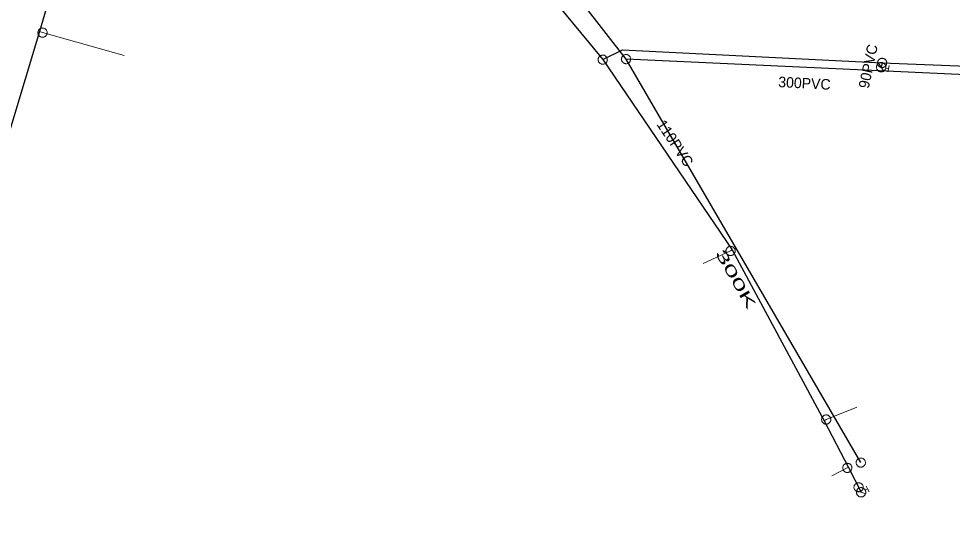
# Model space of a CAD drawing. Extents: x -741806 to -738704, y -1059275 to -1055387.
# Drawn here: x -740471.9 to -740383.1, y -1057505.9 to -1057458.7 of the extents above; entities that cross this region are included whole.
import ezdxf

# ---------------------------------------------------------------- set-up
doc = ezdxf.new("R2010")
doc.units = 0
doc.header["$LTSCALE"] = 0.4
for name, color, linetype, lineweight in [('2', 7, 'Continuous', 25), ('21', 7, 'Continuous', 13), ('3', 7, 'Continuous', 13), ('50', 7, 'Continuous', 13), ('51', 7, 'Continuous', 13), ('52', 7, 'Continuous', 25)]:
    doc.layers.add(name, color=color, linetype=linetype, lineweight=lineweight)
doc.layers.add('5', color=7, linetype='Continuous')
doc.layers.add('53', color=7, linetype='Continuous')

msp = doc.modelspace()

# ---------------------------------------------------------------- linework, layer by layer
at = {"layer": '2'}
for points in [[(-740391.767, -1057500.943), (-740414.1, -1057462.575), (-740436.364, -1057433.99), (-740463.206, -1057418.767)], [(-740262.282, -1057468.655), (-740309.544, -1057466.825), (-740348.973, -1057465.28), (-740379.006, -1057464.2), (-740414.1, -1057462.575)]]:
    msp.add_lwpolyline(points, dxfattribs=at)
at = {"layer": '21'}
for points in [[(-740469.89, -1057459.936), (-740469.611, -1057460.054), (-740461.851, -1057462.24)], [(-740404.013, -1057480.723), (-740404.157, -1057480.815), (-740406.774, -1057482.007)], [(-740395.265, -1057496.955), (-740395.061, -1057496.845), (-740392.149, -1057495.669)], [(-740392.936, -1057501.415), (-740393.052, -1057501.45), (-740394.509, -1057502.191)]]:
    msp.add_lwpolyline(points, dxfattribs=at)
at = {"layer": '3'}
for points in [[(-740414.319, -1057462.196), (-740414.357, -1057462.221), (-740414.392, -1057462.25), (-740414.425, -1057462.283), (-740414.453, -1057462.318), (-740414.478, -1057462.356), (-740414.499, -1057462.398), (-740414.515, -1057462.44), (-740414.527, -1057462.485), (-740414.533, -1057462.53), (-740414.536, -1057462.575), (-740414.533, -1057462.621), (-740414.527, -1057462.667), (-740414.514, -1057462.71), (-740414.498, -1057462.753), (-740414.477, -1057462.794), (-740414.452, -1057462.833), (-740414.422, -1057462.868), (-740414.391, -1057462.9), (-740414.354, -1057462.929), (-740414.316, -1057462.954), (-740414.275, -1057462.974), (-740414.233, -1057462.99), (-740414.188, -1057463.002), (-740414.143, -1057463.009), (-740414.097, -1057463.011), (-740414.051, -1057463.008), (-740414.006, -1057463.002), (-740413.962, -1057462.989), (-740413.919, -1057462.973), (-740413.878, -1057462.951), (-740413.84, -1057462.927), (-740413.805, -1057462.898), (-740413.772, -1057462.865), (-740413.744, -1057462.829), (-740413.719, -1057462.792), (-740413.698, -1057462.75), (-740413.682, -1057462.708), (-740413.67, -1057462.663), (-740413.664, -1057462.618), (-740413.661, -1057462.573), (-740413.664, -1057462.527), (-740413.671, -1057462.481), (-740413.683, -1057462.437), (-740413.699, -1057462.395), (-740413.721, -1057462.354), (-740413.745, -1057462.315), (-740413.774, -1057462.28), (-740413.807, -1057462.248), (-740413.843, -1057462.219), (-740413.882, -1057462.194), (-740413.922, -1057462.174), (-740413.965, -1057462.157), (-740414.009, -1057462.146), (-740414.054, -1057462.139), (-740414.1, -1057462.137), (-740414.146, -1057462.139), (-740414.191, -1057462.146), (-740414.236, -1057462.159), (-740414.278, -1057462.175), (-740414.319, -1057462.195)], [(-740391.986, -1057500.564), (-740392.024, -1057500.589), (-740392.059, -1057500.618), (-740392.092, -1057500.651), (-740392.12, -1057500.686), (-740392.145, -1057500.724), (-740392.166, -1057500.766), (-740392.182, -1057500.808), (-740392.194, -1057500.853), (-740392.2, -1057500.898), (-740392.203, -1057500.943), (-740392.2, -1057500.989), (-740392.194, -1057501.035), (-740392.181, -1057501.078), (-740392.165, -1057501.121), (-740392.144, -1057501.162), (-740392.119, -1057501.201), (-740392.089, -1057501.236), (-740392.058, -1057501.268), (-740392.021, -1057501.297), (-740391.983, -1057501.322), (-740391.942, -1057501.342), (-740391.9, -1057501.358), (-740391.855, -1057501.37), (-740391.81, -1057501.377), (-740391.764, -1057501.379), (-740391.718, -1057501.376), (-740391.673, -1057501.37), (-740391.629, -1057501.357), (-740391.586, -1057501.341), (-740391.545, -1057501.319), (-740391.507, -1057501.295), (-740391.472, -1057501.266), (-740391.439, -1057501.233), (-740391.411, -1057501.197), (-740391.386, -1057501.16), (-740391.365, -1057501.118), (-740391.349, -1057501.076), (-740391.337, -1057501.031), (-740391.331, -1057500.986), (-740391.328, -1057500.941), (-740391.331, -1057500.895), (-740391.338, -1057500.849), (-740391.35, -1057500.805), (-740391.366, -1057500.763), (-740391.388, -1057500.722), (-740391.412, -1057500.683), (-740391.441, -1057500.648), (-740391.474, -1057500.616), (-740391.51, -1057500.587), (-740391.549, -1057500.562), (-740391.589, -1057500.542), (-740391.632, -1057500.525), (-740391.676, -1057500.514), (-740391.721, -1057500.507), (-740391.767, -1057500.505), (-740391.813, -1057500.507), (-740391.858, -1057500.514), (-740391.903, -1057500.527), (-740391.945, -1057500.543), (-740391.986, -1057500.563)]]:
    msp.add_lwpolyline(points, dxfattribs=at)
at = {"layer": '50'}
for p, q in [((-740389.831, -1057463.35), (-740390.075, -1057462.973)), ((-740389.831, -1057463.35), (-740389.591, -1057463.723)), ((-740389.393, -1057463.442), (-740389.148, -1057463.494)), ((-740389.212, -1057463.794), (-740389.148, -1057463.494)), ((-740389.084, -1057463.193), (-740389.148, -1057463.494)), ((-740391.345, -1057503.564), (-740391.121, -1057503.45)), ((-740391.261, -1057503.175), (-740391.121, -1057503.45)), ((-740390.982, -1057503.723), (-740391.121, -1057503.45)), ((-740391.743, -1057503.768), (-740392.169, -1057503.629)), ((-740391.743, -1057503.768), (-740391.322, -1057503.907))]:
    msp.add_line(p, q, dxfattribs=at)
for points in [[(-740389.927, -1057463.783), (-740389.879, -1057463.79), (-740389.833, -1057463.795), (-740389.785, -1057463.792), (-740389.739, -1057463.784), (-740389.696, -1057463.774), (-740389.651, -1057463.756), (-740389.61, -1057463.735), (-740389.569, -1057463.71), (-740389.533, -1057463.682), (-740389.501, -1057463.648), (-740389.471, -1057463.612), (-740389.443, -1057463.574), (-740389.424, -1057463.531), (-740389.406, -1057463.488), (-740389.394, -1057463.444), (-740389.387, -1057463.398), (-740389.383, -1057463.353), (-740389.386, -1057463.305), (-740389.393, -1057463.259), (-740389.405, -1057463.212), (-740389.422, -1057463.17), (-740389.442, -1057463.128), (-740389.468, -1057463.089), (-740389.496, -1057463.053), (-740389.529, -1057463.018), (-740389.565, -1057462.988), (-740389.604, -1057462.963), (-740389.646, -1057462.94), (-740389.69, -1057462.926), (-740389.733, -1057462.91), (-740389.781, -1057462.903), (-740389.828, -1057462.901), (-740389.872, -1057462.903), (-740389.92, -1057462.909), (-740389.965, -1057462.922), (-740390.009, -1057462.937), (-740390.049, -1057462.959), (-740390.09, -1057462.984), (-740390.128, -1057463.014), (-740390.159, -1057463.047), (-740390.189, -1057463.084), (-740390.214, -1057463.123), (-740390.237, -1057463.162), (-740390.255, -1057463.208), (-740390.267, -1057463.253), (-740390.274, -1057463.298), (-740390.276, -1057463.345), (-740390.274, -1057463.392), (-740390.268, -1057463.438), (-740390.255, -1057463.484), (-740390.24, -1057463.526), (-740390.218, -1057463.57), (-740390.194, -1057463.608), (-740390.166, -1057463.644), (-740390.131, -1057463.676), (-740390.096, -1057463.708), (-740390.057, -1057463.734), (-740390.015, -1057463.753), (-740389.972, -1057463.77)], [(-740391.544, -1057504.165), (-740391.502, -1057504.14), (-740391.463, -1057504.115), (-740391.428, -1057504.082), (-740391.398, -1057504.048), (-740391.371, -1057504.012), (-740391.347, -1057503.97), (-740391.328, -1057503.928), (-740391.312, -1057503.883), (-740391.301, -1057503.838), (-740391.298, -1057503.791), (-740391.297, -1057503.745), (-740391.3, -1057503.698), (-740391.312, -1057503.652), (-740391.326, -1057503.608), (-740391.344, -1057503.565), (-740391.367, -1057503.526), (-740391.392, -1057503.488), (-740391.425, -1057503.453), (-740391.46, -1057503.421), (-740391.498, -1057503.393), (-740391.538, -1057503.37), (-740391.58, -1057503.35), (-740391.625, -1057503.336), (-740391.669, -1057503.326), (-740391.717, -1057503.32), (-740391.763, -1057503.319), (-740391.809, -1057503.324), (-740391.856, -1057503.333), (-740391.9, -1057503.349), (-740391.943, -1057503.365), (-740391.985, -1057503.389), (-740392.022, -1057503.417), (-740392.055, -1057503.447), (-740392.089, -1057503.482), (-740392.116, -1057503.52), (-740392.14, -1057503.559), (-740392.158, -1057503.602), (-740392.175, -1057503.647), (-740392.184, -1057503.694), (-740392.188, -1057503.739), (-740392.188, -1057503.787), (-740392.183, -1057503.833), (-740392.176, -1057503.877), (-740392.161, -1057503.925), (-740392.143, -1057503.967), (-740392.119, -1057504.007), (-740392.091, -1057504.044), (-740392.06, -1057504.08), (-740392.027, -1057504.111), (-740391.987, -1057504.139), (-740391.949, -1057504.162), (-740391.905, -1057504.182), (-740391.862, -1057504.196), (-740391.817, -1057504.207), (-740391.77, -1057504.21), (-740391.723, -1057504.213), (-740391.676, -1057504.208), (-740391.631, -1057504.197), (-740391.587, -1057504.183)]]:
    msp.add_lwpolyline(points, close=True, dxfattribs=at)
at = {"layer": '51'}
for points in [[(-740469.174, -1057460.054), (-740469.176, -1057460.009), (-740469.183, -1057459.964), (-740469.195, -1057459.919), (-740469.211, -1057459.877), (-740469.232, -1057459.836), (-740469.257, -1057459.797), (-740469.286, -1057459.762), (-740469.318, -1057459.729), (-740469.354, -1057459.701), (-740469.392, -1057459.676), (-740469.433, -1057459.655), (-740469.476, -1057459.638), (-740469.52, -1057459.626), (-740469.565, -1057459.619), (-740469.611, -1057459.617), (-740469.657, -1057459.619), (-740469.702, -1057459.626), (-740469.746, -1057459.638), (-740469.789, -1057459.655), (-740469.83, -1057459.676), (-740469.868, -1057459.701), (-740469.904, -1057459.729), (-740469.936, -1057459.762), (-740469.965, -1057459.797), (-740469.99, -1057459.836), (-740470.011, -1057459.877), (-740470.027, -1057459.919), (-740470.039, -1057459.964), (-740470.046, -1057460.009), (-740470.049, -1057460.055), (-740470.046, -1057460.1), (-740470.039, -1057460.145), (-740470.027, -1057460.19), (-740470.011, -1057460.232), (-740469.99, -1057460.273), (-740469.965, -1057460.312), (-740469.936, -1057460.347), (-740469.904, -1057460.38), (-740469.868, -1057460.408), (-740469.83, -1057460.433), (-740469.789, -1057460.454), (-740469.746, -1057460.471), (-740469.702, -1057460.482), (-740469.657, -1057460.49), (-740469.611, -1057460.492), (-740469.565, -1057460.49), (-740469.52, -1057460.482), (-740469.476, -1057460.471), (-740469.433, -1057460.454), (-740469.392, -1057460.433), (-740469.354, -1057460.408), (-740469.318, -1057460.38), (-740469.286, -1057460.347), (-740469.257, -1057460.312), (-740469.232, -1057460.273), (-740469.211, -1057460.232), (-740469.195, -1057460.19), (-740469.183, -1057460.145), (-740469.176, -1057460.1), (-740469.174, -1057460.055)], [(-740389.301, -1057462.955), (-740389.301, -1057462.91), (-740389.306, -1057462.864), (-740389.315, -1057462.819), (-740389.329, -1057462.776), (-740389.348, -1057462.734), (-740389.371, -1057462.694), (-740389.398, -1057462.658), (-740389.429, -1057462.623), (-740389.463, -1057462.593), (-740389.5, -1057462.566), (-740389.54, -1057462.543), (-740389.582, -1057462.524), (-740389.625, -1057462.51), (-740389.67, -1057462.501), (-740389.716, -1057462.497), (-740389.762, -1057462.496), (-740389.807, -1057462.501), (-740389.852, -1057462.511), (-740389.895, -1057462.526), (-740389.937, -1057462.545), (-740389.977, -1057462.568), (-740390.014, -1057462.594), (-740390.048, -1057462.625), (-740390.078, -1057462.659), (-740390.105, -1057462.696), (-740390.128, -1057462.736), (-740390.146, -1057462.777), (-740390.161, -1057462.822), (-740390.17, -1057462.866), (-740390.175, -1057462.912), (-740390.174, -1057462.957), (-740390.17, -1057463.003), (-740390.16, -1057463.048), (-740390.146, -1057463.091), (-740390.127, -1057463.133), (-740390.104, -1057463.173), (-740390.077, -1057463.209), (-740390.046, -1057463.244), (-740390.012, -1057463.274), (-740389.975, -1057463.301), (-740389.935, -1057463.324), (-740389.893, -1057463.343), (-740389.85, -1057463.356), (-740389.805, -1057463.366), (-740389.759, -1057463.37), (-740389.713, -1057463.371), (-740389.668, -1057463.365), (-740389.623, -1057463.356), (-740389.58, -1057463.341), (-740389.538, -1057463.322), (-740389.498, -1057463.299), (-740389.461, -1057463.273), (-740389.428, -1057463.242), (-740389.397, -1057463.208), (-740389.37, -1057463.171), (-740389.347, -1057463.131), (-740389.329, -1057463.09), (-740389.315, -1057463.045), (-740389.305, -1057463.001), (-740389.301, -1057462.956)], [(-740404.526, -1057481.048), (-740404.5, -1057481.085), (-740404.47, -1057481.119), (-740404.436, -1057481.15), (-740404.4, -1057481.177), (-740404.361, -1057481.201), (-740404.319, -1057481.22), (-740404.276, -1057481.235), (-740404.231, -1057481.245), (-740404.185, -1057481.25), (-740404.14, -1057481.251), (-740404.094, -1057481.246), (-740404.049, -1057481.238), (-740404.005, -1057481.225), (-740403.963, -1057481.206), (-740403.923, -1057481.183), (-740403.885, -1057481.157), (-740403.851, -1057481.127), (-740403.82, -1057481.094), (-740403.793, -1057481.056), (-740403.77, -1057481.017), (-740403.751, -1057480.975), (-740403.735, -1057480.932), (-740403.726, -1057480.887), (-740403.72, -1057480.842), (-740403.72, -1057480.796), (-740403.724, -1057480.75), (-740403.733, -1057480.706), (-740403.747, -1057480.662), (-740403.765, -1057480.62), (-740403.787, -1057480.579), (-740403.814, -1057480.543), (-740403.844, -1057480.509), (-740403.878, -1057480.477), (-740403.914, -1057480.45), (-740403.953, -1057480.426), (-740403.995, -1057480.407), (-740404.039, -1057480.393), (-740404.083, -1057480.382), (-740404.129, -1057480.378), (-740404.174, -1057480.377), (-740404.22, -1057480.381), (-740404.265, -1057480.389), (-740404.308, -1057480.404), (-740404.351, -1057480.421), (-740404.391, -1057480.444), (-740404.429, -1057480.47), (-740404.462, -1057480.501), (-740404.494, -1057480.534), (-740404.521, -1057480.571), (-740404.544, -1057480.611), (-740404.563, -1057480.652), (-740404.579, -1057480.695), (-740404.588, -1057480.74), (-740404.594, -1057480.785), (-740404.594, -1057480.831), (-740404.59, -1057480.877), (-740404.581, -1057480.921), (-740404.567, -1057480.966), (-740404.549, -1057481.008), (-740404.527, -1057481.047)], [(-740394.624, -1057496.845), (-740394.625, -1057496.8), (-740394.633, -1057496.755), (-740394.645, -1057496.71), (-740394.661, -1057496.668), (-740394.682, -1057496.627), (-740394.706, -1057496.588), (-740394.736, -1057496.553), (-740394.768, -1057496.52), (-740394.804, -1057496.492), (-740394.842, -1057496.467), (-740394.883, -1057496.446), (-740394.926, -1057496.429), (-740394.97, -1057496.417), (-740395.015, -1057496.41), (-740395.061, -1057496.408), (-740395.107, -1057496.41), (-740395.152, -1057496.417), (-740395.196, -1057496.429), (-740395.239, -1057496.446), (-740395.28, -1057496.467), (-740395.318, -1057496.492), (-740395.353, -1057496.52), (-740395.386, -1057496.553), (-740395.415, -1057496.588), (-740395.44, -1057496.627), (-740395.461, -1057496.668), (-740395.477, -1057496.71), (-740395.489, -1057496.755), (-740395.496, -1057496.8), (-740395.499, -1057496.846), (-740395.496, -1057496.891), (-740395.489, -1057496.936), (-740395.477, -1057496.981), (-740395.461, -1057497.023), (-740395.44, -1057497.064), (-740395.415, -1057497.103), (-740395.386, -1057497.138), (-740395.353, -1057497.171), (-740395.318, -1057497.199), (-740395.28, -1057497.224), (-740395.239, -1057497.245), (-740395.196, -1057497.262), (-740395.152, -1057497.273), (-740395.107, -1057497.281), (-740395.061, -1057497.283), (-740395.015, -1057497.281), (-740394.97, -1057497.273), (-740394.926, -1057497.262), (-740394.883, -1057497.245), (-740394.842, -1057497.224), (-740394.804, -1057497.199), (-740394.768, -1057497.171), (-740394.736, -1057497.138), (-740394.706, -1057497.103), (-740394.682, -1057497.064), (-740394.661, -1057497.023), (-740394.645, -1057496.981), (-740394.633, -1057496.936), (-740394.625, -1057496.891), (-740394.624, -1057496.846)], [(-740393.47, -1057501.576), (-740393.455, -1057501.619), (-740393.435, -1057501.66), (-740393.41, -1057501.699), (-740393.383, -1057501.735), (-740393.351, -1057501.768), (-740393.315, -1057501.798), (-740393.278, -1057501.823), (-740393.237, -1057501.845), (-740393.195, -1057501.862), (-740393.151, -1057501.874), (-740393.106, -1057501.883), (-740393.06, -1057501.886), (-740393.014, -1057501.885), (-740392.969, -1057501.879), (-740392.924, -1057501.867), (-740392.881, -1057501.852), (-740392.84, -1057501.832), (-740392.801, -1057501.808), (-740392.765, -1057501.779), (-740392.732, -1057501.747), (-740392.703, -1057501.712), (-740392.677, -1057501.675), (-740392.656, -1057501.634), (-740392.638, -1057501.592), (-740392.626, -1057501.547), (-740392.617, -1057501.502), (-740392.614, -1057501.457), (-740392.616, -1057501.411), (-740392.622, -1057501.365), (-740392.633, -1057501.321), (-740392.649, -1057501.278), (-740392.669, -1057501.237), (-740392.693, -1057501.198), (-740392.721, -1057501.162), (-740392.753, -1057501.129), (-740392.788, -1057501.099), (-740392.826, -1057501.074), (-740392.866, -1057501.052), (-740392.909, -1057501.036), (-740392.952, -1057501.023), (-740392.998, -1057501.015), (-740393.044, -1057501.011), (-740393.089, -1057501.013), (-740393.135, -1057501.019), (-740393.179, -1057501.03), (-740393.223, -1057501.045), (-740393.263, -1057501.066), (-740393.302, -1057501.089), (-740393.338, -1057501.118), (-740393.372, -1057501.15), (-740393.401, -1057501.185), (-740393.427, -1057501.222), (-740393.448, -1057501.263), (-740393.465, -1057501.305), (-740393.478, -1057501.35), (-740393.486, -1057501.395), (-740393.489, -1057501.44), (-740393.488, -1057501.487), (-740393.481, -1057501.532), (-740393.47, -1057501.575)], [(-740391.782, -1057503.681), (-740391.742, -1057503.659), (-740391.705, -1057503.632), (-740391.671, -1057503.601), (-740391.641, -1057503.568), (-740391.614, -1057503.53), (-740391.59, -1057503.49), (-740391.572, -1057503.449), (-740391.557, -1057503.405), (-740391.549, -1057503.36), (-740391.544, -1057503.315), (-740391.544, -1057503.269), (-740391.548, -1057503.223), (-740391.557, -1057503.178), (-740391.571, -1057503.135), (-740391.591, -1057503.093), (-740391.613, -1057503.053), (-740391.64, -1057503.016), (-740391.671, -1057502.983), (-740391.705, -1057502.952), (-740391.743, -1057502.925), (-740391.782, -1057502.902), (-740391.823, -1057502.883), (-740391.867, -1057502.87), (-740391.912, -1057502.86), (-740391.958, -1057502.855), (-740392.004, -1057502.855), (-740392.049, -1057502.86), (-740392.094, -1057502.87), (-740392.137, -1057502.884), (-740392.18, -1057502.902), (-740392.218, -1057502.925), (-740392.255, -1057502.952), (-740392.29, -1057502.983), (-740392.32, -1057503.016), (-740392.347, -1057503.053), (-740392.371, -1057503.093), (-740392.389, -1057503.135), (-740392.403, -1057503.179), (-740392.412, -1057503.223), (-740392.417, -1057503.269), (-740392.417, -1057503.315), (-740392.413, -1057503.361), (-740392.403, -1057503.405), (-740392.389, -1057503.449), (-740392.37, -1057503.491), (-740392.348, -1057503.531), (-740392.32, -1057503.567), (-740392.29, -1057503.601), (-740392.256, -1057503.632), (-740392.218, -1057503.659), (-740392.179, -1057503.681), (-740392.137, -1057503.701), (-740392.093, -1057503.714), (-740392.049, -1057503.724), (-740392.003, -1057503.729), (-740391.957, -1057503.729), (-740391.912, -1057503.724), (-740391.867, -1057503.714), (-740391.823, -1057503.7), (-740391.782, -1057503.682)]]:
    msp.add_lwpolyline(points, dxfattribs=at)
msp.add_lwpolyline([(-740416.04, -1057462.959), (-740416.006, -1057462.929), (-740415.976, -1057462.894), (-740415.949, -1057462.857), (-740415.927, -1057462.817), (-740415.908, -1057462.775), (-740415.894, -1057462.731), (-740415.886, -1057462.686), (-740415.881, -1057462.641), (-740415.882, -1057462.595), (-740415.887, -1057462.55), (-740415.897, -1057462.505), (-740415.911, -1057462.461), (-740415.93, -1057462.419), (-740415.953, -1057462.38), (-740415.981, -1057462.344), (-740416.012, -1057462.309), (-740416.046, -1057462.279), (-740416.083, -1057462.253), (-740416.124, -1057462.23), (-740416.166, -1057462.212), (-740416.209, -1057462.199), (-740416.254, -1057462.189), (-740416.3, -1057462.185), (-740416.345, -1057462.185), (-740416.391, -1057462.191), (-740416.436, -1057462.201), (-740416.479, -1057462.215), (-740416.521, -1057462.235), (-740416.56, -1057462.258), (-740416.598, -1057462.285), (-740416.63, -1057462.316), (-740416.661, -1057462.35), (-740416.688, -1057462.388), (-740416.71, -1057462.427), (-740416.728, -1057462.469), (-740416.742, -1057462.513), (-740416.751, -1057462.558), (-740416.756, -1057462.604), (-740416.754, -1057462.649), (-740416.75, -1057462.694), (-740416.74, -1057462.739), (-740416.725, -1057462.783), (-740416.706, -1057462.824), (-740416.683, -1057462.864), (-740416.656, -1057462.901), (-740416.625, -1057462.935), (-740416.59, -1057462.965), (-740416.553, -1057462.991), (-740416.513, -1057463.014), (-740416.471, -1057463.032), (-740416.427, -1057463.045), (-740416.383, -1057463.055), (-740416.337, -1057463.059), (-740416.291, -1057463.059), (-740416.245, -1057463.053), (-740416.2, -1057463.044), (-740416.158, -1057463.029), (-740416.115, -1057463.01), (-740416.076, -1057462.986)], close=True, dxfattribs=at)
at = {"layer": '52'}
msp.add_line((-740389.738, -1057462.933), (-740389.827, -1057463.351), dxfattribs=at)
for points in [[(-740407.857, -1057263.098), (-740439.467, -1057360.607), (-740447.059, -1057384.081), (-740447.248, -1057384.679), (-740452.412, -1057401.031), (-740457.603, -1057418.83), (-740467.015, -1057450.047), (-740468.397, -1057454.838), (-740469.89, -1057459.936), (-740472.616, -1057468.997), (-740478.407, -1057487.088), (-740480.659, -1057495.081), (-740486.488, -1057512.648), (-740486.78, -1057514.456), (-740493.754, -1057537.497), (-740495.864, -1057543.049), (-740500.778, -1057560.762), (-740501.975, -1057565.431)], [(-740457.603, -1057418.83), (-740443.921, -1057429.208), (-740416.318, -1057462.622)], [(-740416.318, -1057462.622), (-740414.453, -1057461.699), (-740389.738, -1057462.933), (-740263.11, -1057467.919)], [(-740416.318, -1057462.622), (-740404.013, -1057480.723), (-740395.265, -1057496.955), (-740392.936, -1057501.415), (-740391.739, -1057503.766)]]:
    msp.add_lwpolyline(points, dxfattribs=at)

# ---------------------------------------------------------------- texts
at = {"layer": '5'}
msp.add_text('300PVC', height=1, rotation=357, dxfattribs=at).set_placement((-740399.641, -1057465.232))
at = {"layer": '5', "width": 2}
msp.add_text('300K', height=1, rotation=300, dxfattribs=at).set_placement((-740405.655, -1057481.03))
at = {"layer": '53'}
for s, rotation, p in [('90PVC ', 78, (-740391.021, -1057465.433)), ('110PVC', 304, (-740411.243, -1057468.778))]:
    msp.add_text(s, height=1, rotation=rotation, dxfattribs=at).set_placement(p)

doc.saveas('drawing.dxf')
